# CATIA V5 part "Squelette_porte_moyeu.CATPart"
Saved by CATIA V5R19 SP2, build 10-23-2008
Part number: squelette_porte_moyeu
Bounding box of the stored display mesh (mm): x -20 to 140, y -800 to -770, z -140 to 140
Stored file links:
  C:\Users\Pauline\Desktop\CFAO_Catia\Compte_rendu\pmayet_assemblage_animation4\Squelette_porte_moyeu.CATPart
  C:\Users\Pauline\Desktop\CFAO_Catia\Compte_rendu\pmayet_assemblage_animation4\pmayet_assemblage_animation.CATProduct
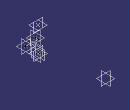
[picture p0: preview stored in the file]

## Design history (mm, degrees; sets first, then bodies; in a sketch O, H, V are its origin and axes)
Set1
  Point1 to Point5: linked copy from another document
Set2
  Line1: type PtPt, FirstPoint Point1, SecondPoint Point2
  Plane1: type OffsetPt, RefPlane zx-plane, RefPoint Point1
  Plane2: type OffsetPt, RefPlane yz-plane, RefPoint Point1
  Plane3: type OffsetPt, RefPlane xy-plane, RefPoint Point1
  Plane4: type OffsetPt, RefPlane xy-plane, RefPoint Point3
  Plane5: type OffsetPt, RefPlane xy-plane, RefPoint Point4
  Plane6: type OffsetPt, RefPlane zx-plane, RefPoint Point4
  Plane7: type OffsetPt, RefPlane zx-plane, RefPoint Point3
  Line2: type PtPt, FirstPoint Point2, SecondPoint Point5
  Plane8: type OffsetPt, RefPlane Plane3, RefPoint Point5
  Plane9: type OffsetPt, RefPlane Plane2, RefPoint Point5
  Plane10: type OffsetPt, RefPlane Plane1, RefPoint Point5
  Line3: type Angle, RefPoint Point4, Curve Line2, Start -20, End 20, Angle 0
  Plane11: type OffsetPt, RefPlane Plane2, RefPoint vertex of Line3
  Plane12: type OffsetPt, RefPlane Plane11, RefPoint vertex of Line3
Body1 (main body)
